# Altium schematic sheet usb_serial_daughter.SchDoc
size 420 x 297 mm; Date: TEST; Sheet_Text_ProjectName: ApolloEcho_Dev_Kit; Sheet_Text_Author: mtnguyen; Sheet_Text_Title: USB Serial; Sheet_Text_Rev: 1.0.0; Sheet_Text_Date: Dec 03, 24; SPICEModelCacheFSQVNMCJ: <root> / <DocumentId>FSQVNMCJ</DocumentId> / <CacheFrame Number="0"> / <Model Name="emk105bj105_v-f" Kind="CKT"> / <Text>* EMK105BJ105_V-F     SPICE MODEL  ( General Type ) / *-------------------------------------------------------------------------------------------------------- / * Model Generated by TAIYO YUDEN Corporation (http://www.ty-top.com) / * Version 1.0 / * TAIYO YUDEN Control No. 170508_130520 / * Copyright(c) 2012 TAIYO YUDEN CO.,LTD. All Rights Reserved. / *-------------------------------------------------------------------------------------------------------- / * / * Products Name : Multilayer Ceramic Capacitors / * / * Characteristics : / *     Capacitance : 1 uF , Rated Voltage : 16V , TCC : X5R / *     Case Size : 1.0 x 0.5 / 0.039 x 0.02 [mm/inch] , Thickness : 0.5 / 0.02 [mm/inch] / *     (Conditions: Temperature = 25 degC , DC Bias Current/Voltage = 0A / 0V) / * / * Frequency Range : 40Hz - 3GHz / * / * External Node Assignments : / * / *  1  o---¦ ¦---o  2 / * / *-------------------------------------------------------------------------------------------------------- / .SubCkt EMK105BJ105_V-F 1 2 / **************************** / C0 1 110 0.68309u / Cm 1 101 0.26053u / C1 101 102 0.94076u / Rc1 101 102 1.9029k / C2 102 103 0.66707u / Rc2 102 103 120.36 / C3 103 110 0.57203u / Rc3 103 110 2.1097 / C2m 1 301 0.1871u / C21 301 302 3.2494u / Rc21 301 302 1.1117k / C22 302 303 2.1014u / Rc22 302 303 1.484k / C23 303 304 2.1172u / Rc23 303 304 1.3876k / C24 304 305 0.75729u / Rc24 304 305 332.59 / C25 305 306 0.94401u / Rc25 305 306 249.09 / C26 306 307 0.34674u / Rc26 306 307 28.352 / C27 307 308 0.37158u / Rc27 307 308 19.989 / C28 308 309 0.17933u / Rc28 308 309 31.748 / C29 309 110 0.016445u / Rc29 309 110 1.0592 / Rp0 1 110 100Meg / L0 110 120 0.2216n / Lm 120 130 0.1509n / L1 120 121 0.12659n / RL1 121 130 0.85161 / L2 120 122 0.15996n / RL2 122 130 0.42469 / L3 120 123 7.9543n / RL3 123 130 0.54643m / CR 120 124 0.24334u / LR 124 125 0.090738n / RR 125 130 68.076m / CL 130 140 2.7354p / LL 130 140 0.10762n / RL 130 140 50.614 / Rs 140 2 7.5416m / **************************** / .ends EMK105BJ105_V-F</Text> / </Model> / </CacheFrame> / </root>
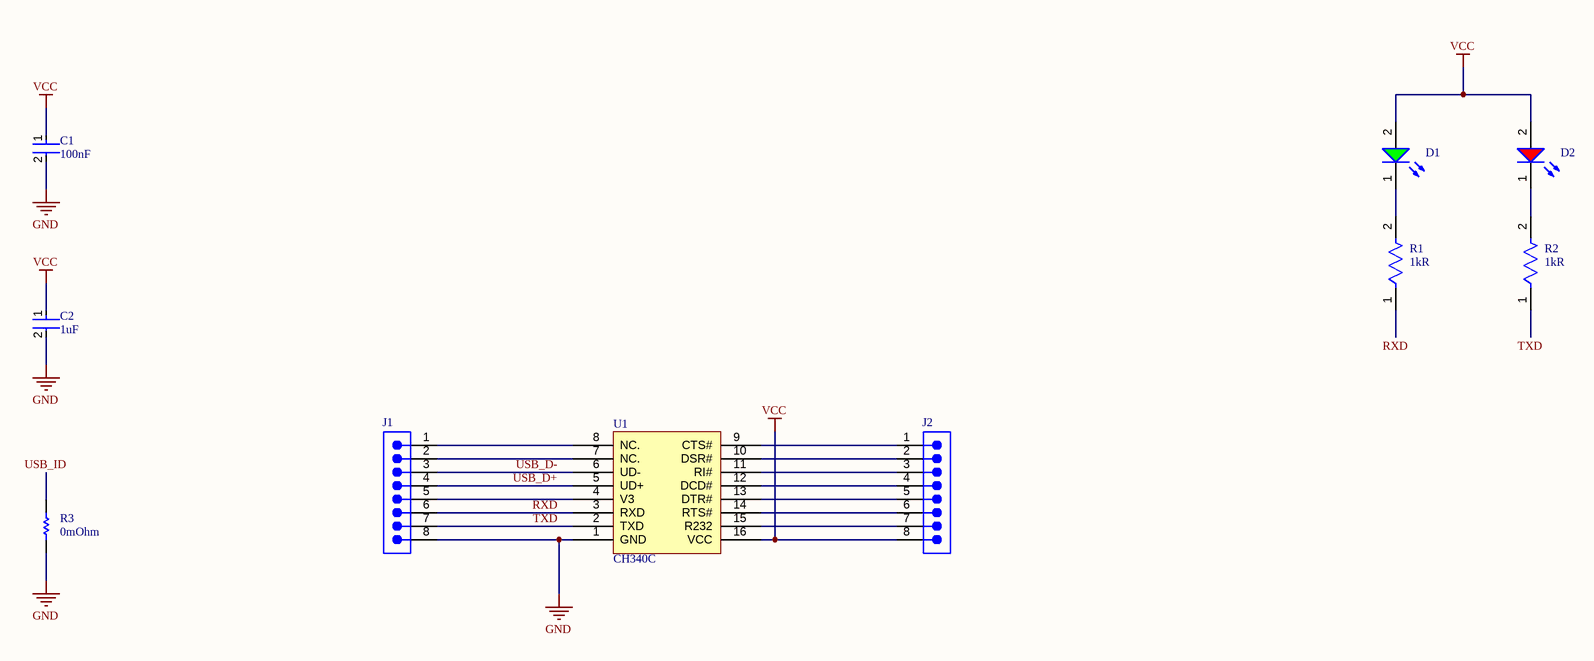
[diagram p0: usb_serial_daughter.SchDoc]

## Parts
C1  Capacitance: 100nF  [FP-0402-L_1_0_1-W_0_5_0_1-IPC_C]  (hidden comment: 0402ZD104KAT2A)
C2  Capacitance: 1uF  [FP-0402-L_1_0_0_05-W_0_5-IPC_A]  (hidden comment: EMK105BJ105KV-F)
D1  150060VS75000  [WL-SMCW_0603_150060xx75000]  (value not drawn)
D2  150060RS75000  [WL-SMCW_0603_150060xx75000]  (value not drawn)
J1  61300811121  [61300811121]  (value not drawn)
J2  61300811121  [61300811121]  (value not drawn)
R1  Resistance: 1kR  [FP-RMCF0402-IPC_A]  (hidden comment: RMCF0402FT1K00)
R2  Resistance: 1kR  [FP-RMCF0402-IPC_A]  (hidden comment: RMCF0402FT1K00)
R3  Resistance: 0mOhm  [RESC1005X40X25LL05T05]  (hidden comment: ERJ2GE0R00X)
U1  CH340C  [CH340C]

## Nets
GND: C1.2 C2.2 J1.8 R3.1 U1.1(GND)
VCC: C1.1 C2.1 D1.2(A) D2.2(A) J2.8 U1.16(VCC)
RXD: J1.6 R1.1 U1.3(RXD)
TXD: J1.7 R2.1 U1.2(TXD)
USB_D+: J1.4 U1.5(UD+)
USB_D-: J1.3 U1.6(UD-)
USB_ID: R3.2
NetD1_1: D1.1(K) R1.2
NetD2_1: D2.1(K) R2.2
NetJ1_1: J1.1 U1.8(NC.)
NetJ1_2: J1.2 U1.7(NC.)
NetJ1_5: J1.5 U1.4(V3)
NetJ2_1: J2.1 U1.9(CTS#)
NetJ2_2: J2.2 U1.10(DSR#)
NetJ2_3: J2.3 U1.11(RI#)
NetJ2_4: J2.4 U1.12(DCD#)
NetJ2_5: J2.5 U1.13(DTR#)
NetJ2_6: J2.6 U1.14(RTS#)
NetJ2_7: J2.7 U1.15(R232)

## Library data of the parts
C1 = CMP-2008-02878-3: General Purpose Ceramic Capacitor, 0402, 100nF, 10%, X5R, 15%, 10V; Dissipation Factor: 5%; Insulation Resistance: 100GR
C2 = CMP-14477-000104-2: None; Tolerance: 10%; Voltage Rating: 16V; Dielectric: X5R
D1 = CMP-1426-00006-7: WURTH ELEKTRONIK - 150060VS75000 - LED, Green, SMD, 0603, 30 mA, 2 V, 570 nm; Reverse Voltage: 5V; Power Dissipation: 72mW; Dominant Wavelength: 570nm; Peak Wavelength: 572nm; Forward Current: 100mA; Forward Voltage: 2V; Lens Style: Clear, Rectangular; Test Current: 20mA; Max Junction Temperature (Tj): 95°C; Viewing Angle: 140°; Luminous Intensity: 40mcd
D2 = CMP-1426-00001-4: LED Low-Power Uni-Color Red 630nm 2V 2-Pin Chip 0603(1608Metric) T/R; Max Junction Temperature (Tj): 95°C; Dominant Wavelength: 625nm; Lens Style: Clear, Rectangular; Viewing Angle: 140°; Forward Current: 100mA; Max Reverse Voltage (DC): 5V; Luminous Intensity: 250mcd; Test Current: 20mA; Power Dissipation: 72mW
J1 J2 = CMP-1502-01076-3: NexarPartId: 32855533; Connector Type: Male Pin; Number of Contacts: 8; Voltage Rating: 250V; Current Rating: 3A; Contact Resistance: 20mΩ; Pitch: 2.54mm; Gender: Male
R1 R2 = CMP-26527-000026-1: 1kΩ ±1% 0.063W 0402 Thick Film Chip Resistor AEC-Q200 compliant; Temperature Coefficient: 100ppm/°C; Power Rating: 63mW
R3 = CMP-2000-07451-1: Chip Resistor, 0 Ohm, 0.1 W, -55 to 155 degC, 0402 (1005 Metric), RoHS, Tape and Reel; Manufacturer: Panasonic; Voltage Rating (DC): 50V; Temperature Coefficient: 600ppm/��C; Max Power Dissipation: 100mW; Tolerance: 5%
U1 = CH340C: USB to Serial CH340 IC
